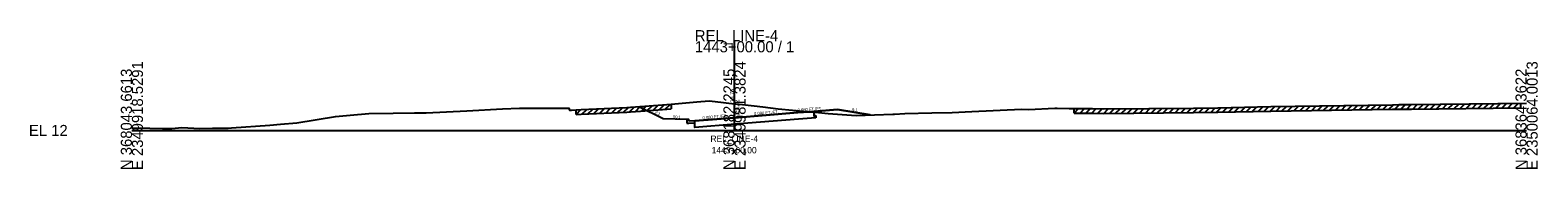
# Model space of a CAD drawing. Extents: x -26 to 2350146, y -10 to 368200.
# Drawn here: x 1974.3 to 2355, y 2990.3 to 3025.3 of the extents above; entities that cross this region are included whole.
import ezdxf

# ---------------------------------------------------------------- set-up
doc = ezdxf.new("R2010")
doc.units = 0
for name, color, linetype in [('RD_GPK_XS_Cell', 7, 'Continuous'), ('RD_XS_Base', 7, 'Continuous'), ('RD_XS_CurbBase', 7, 'Continuous'), ('RD_XS_CurbFront', 7, 'Continuous'), ('RD_XS_CurbTop', 7, 'Continuous'), ('RD_XS_EarthShd', 7, 'Continuous'), ('RD_XS_EwShp', 7, 'Continuous'), ('RD_XS_ExGround', 7, 'Continuous'), ('RD_XS_ExPaveRet', 7, 'Continuous'), ('RD_XS_Pave', 7, 'Continuous'), ('RD_XS_PaveShd', 7, 'Continuous'), ('RD_XS_TieSlope', 7, 'Continuous'), ('RD_XS_TX_Elev_EX', 7, 'Continuous'), ('RD_XS_TX_Elev_PR', 7, 'Continuous'), ('RD_XS_TX_Slope', 7, 'Continuous'), ('RD_XS_TX_Station', 7, 'Continuous'), ('RD_XS_TX_TOC', 7, 'Continuous')]:
    doc.layers.add(name, color=color, linetype=linetype)

msp = doc.modelspace()

# ---------------------------------------------------------------- linework, layer by layer
at = {"layer": 'RD_GPK_XS_Cell'}
for p, q in [((2152.15, 3000), (2152.15, 3022.53)), ((2000, 3000), (2152.15, 3000)), ((2152.15, 3000), (2352.15, 3000))]:
    msp.add_line(p, q, dxfattribs=at)
at = {"layer": 'RD_XS_Base'}
for p, q in [((2172.16, 3004.82), (2172.16, 3003.68)), ((2172.66, 3003.72), (2172.66, 3003.22)), ((2142.15, 3000.78), (2142.15, 3001.9)), ((2152.28, 3001.59), (2142.15, 3000.78)), ((2168.28, 3002.87), (2152.28, 3001.59)), ((2172.66, 3003.22), (2168.28, 3002.87))]:
    msp.add_line(p, q, dxfattribs=at)
at = {"layer": 'RD_XS_CurbBase'}
for p, q in [((2172.66, 3003.72), (2172.16, 3003.68)), ((2140.15, 3002.81), (2140.15, 3001.81)), ((2140.15, 3001.81), (2140.65, 3001.81)), ((2140.65, 3001.81), (2142.15, 3001.9))]:
    msp.add_line(p, q, dxfattribs=at)
at = {"layer": 'RD_XS_CurbFront'}
msp.add_line((2142.15, 3001.9), (2142.15, 3002.4), dxfattribs=at)
at = {"layer": 'RD_XS_CurbTop'}
for p, q in [((2140.65, 3002.81), (2140.15, 3002.81)), ((2140.73, 3002.31), (2140.65, 3002.81)), ((2142.15, 3002.4), (2140.73, 3002.31)), ((2142.15, 3002.42), (2142.15, 3002.4))]:
    msp.add_line(p, q, dxfattribs=at)
at = {"layer": 'RD_XS_EarthShd'}
for p, q in [((2172.16, 3004.82), (2178.15, 3005.3)), ((2178.15, 3005.3), (2186.42, 3003.92)), ((2140.15, 3002.81), (2134.15, 3002.93))]:
    msp.add_line(p, q, dxfattribs=at)
at = {"layer": 'RD_XS_EwShp'}
for points in [[(2140.15, 3002.81), (2134.15, 3002.93), (2128, 3006.01), (2128.39, 3006.04), (2136.18, 3006.6), (2142.67, 3007.22), (2145.77, 3007.51), (2147.25, 3007.32), (2152.15, 3006.75), (2154.13, 3006.52), (2159.32, 3005.95), (2163.16, 3005.5), (2170.45, 3004.8), (2171.11, 3004.73), (2168.15, 3004.5), (2152.15, 3003.22), (2142.15, 3002.4), (2140.73, 3002.31), (2140.65, 3002.81)], [(2172.66, 3003.22), (2168.28, 3002.87), (2152.28, 3001.59), (2142.15, 3000.78), (2142.15, 3001.9), (2142.15, 3002.4), (2152.15, 3003.22), (2168.15, 3004.5), (2171.11, 3004.73), (2172.16, 3004.62), (2172.16, 3003.68), (2172.66, 3003.72)], [(2172.16, 3004.62), (2173.33, 3004.5), (2175.77, 3004.32), (2182.86, 3003.8), (2186.42, 3003.92), (2178.15, 3005.3), (2172.16, 3004.82)], [(2140.15, 3001.81), (2140.65, 3001.81), (2142.15, 3001.9), (2142.15, 3002.4), (2140.73, 3002.31), (2140.65, 3002.81), (2140.15, 3002.81)]]:
    msp.add_lwpolyline(points, close=True, dxfattribs=at)
at = {"layer": 'RD_XS_ExGround'}
msp.add_lwpolyline([(2000, 3000.7), (2004.53, 3000.54), (2007.71, 3000.53), (2010.04, 3000.52), (2012.59, 3000.77), (2017.14, 3000.5), (2020.31, 3000.56), (2024.3, 3000.59), (2025.12, 3000.66), (2034.83, 3001.37), (2037.52, 3001.56), (2041.65, 3001.93), (2051.41, 3003.49), (2056.07, 3003.96), (2058.86, 3004.23), (2059.79, 3004.29), (2065.98, 3004.38), (2071.33, 3004.45), (2073.08, 3004.49), (2074.33, 3004.49), (2084.6, 3004.98), (2093.57, 3005.5), (2097.84, 3005.59), (2099.12, 3005.61), (2102.2, 3005.62), (2106.81, 3005.66), (2109.75, 3005.65), (2110.31, 3005.64), (2110.48, 3005.14), (2110.98, 3005.16), (2112.14, 3005.2), (2113.41, 3005.26), (2125, 3005.8), (2125.85, 3005.86), (2128.39, 3006.04), (2136.18, 3006.6), (2142.67, 3007.22), (2145.77, 3007.51), (2147.25, 3007.32), (2152.15, 3006.75), (2154.13, 3006.52), (2159.32, 3005.95), (2163.16, 3005.5), (2170.45, 3004.8), (2173.33, 3004.5), (2175.77, 3004.32), (2182.86, 3003.8), (2192.16, 3004.11), (2192.57, 3004.12), (2195.14, 3004.25), (2202.01, 3004.48), (2207.08, 3004.55), (2212.08, 3004.81), (2224.65, 3005.35), (2226.36, 3005.33), (2233.07, 3005.65), (2233.6, 3005.6), (2236.69, 3005.54), (2237.89, 3005.51), (2242.52, 3005.53), (2245.37, 3005.46), (2268.08, 3005.64), (2274.22, 3005.74), (2287.55, 3006.03), (2318.26, 3006.5), (2319.89, 3006.52), (2320.35, 3006.53), (2321.19, 3006.54), (2323.13, 3006.55), (2352.15, 3006.87)], dxfattribs=at)
at = {"layer": 'RD_XS_ExPaveRet'}
for p, q in [((2112.14, 3004.06), (2113.34, 3005.26)), ((2112.14, 3004.06), (2112.14, 3005.2)), ((2112.14, 3004.06), (2113.41, 3004.12)), ((2113.41, 3004.12), (2125, 3004.66)), ((2113.64, 3004.13), (2114.84, 3005.33)), ((2115.14, 3004.2), (2116.34, 3005.4)), ((2116.64, 3004.27), (2117.84, 3005.47)), ((2118.14, 3004.34), (2119.34, 3005.54)), ((2119.64, 3004.41), (2120.84, 3005.61)), ((2121.14, 3004.48), (2122.34, 3005.67)), ((2122.64, 3004.55), (2123.84, 3005.74)), ((2124.14, 3004.62), (2125.35, 3005.82)), ((2125, 3004.66), (2125.85, 3004.71)), ((2125.64, 3004.7), (2126.87, 3005.93)), ((2125.85, 3004.71), (2128.39, 3004.89)), ((2127.14, 3004.81), (2128.37, 3006.04)), ((2128.39, 3004.89), (2136.18, 3005.46)), ((2128.64, 3004.91), (2129.87, 3006.14)), ((2130.14, 3005.02), (2131.37, 3006.25)), ((2131.64, 3005.13), (2132.87, 3006.36)), ((2133.14, 3005.24), (2134.37, 3006.47)), ((2134.64, 3005.35), (2135.87, 3006.58)), ((2136.18, 3006.6), (2136.18, 3005.46)), ((2237.89, 3004.37), (2239.04, 3005.52)), ((2237.89, 3004.37), (2237.89, 3005.51)), ((2237.89, 3004.37), (2242.52, 3004.39)), ((2239.39, 3004.37), (2240.54, 3005.52)), ((2240.89, 3004.38), (2242.04, 3005.53)), ((2242.39, 3004.39), (2243.5, 3005.51)), ((2242.52, 3004.39), (2245.37, 3004.32)), ((2243.89, 3004.36), (2245, 3005.47)), ((2245.37, 3004.32), (2268.08, 3004.5)), ((2245.39, 3004.32), (2246.54, 3005.47)), ((2246.89, 3004.33), (2248.04, 3005.48)), ((2248.39, 3004.34), (2249.54, 3005.49)), ((2249.89, 3004.35), (2251.04, 3005.5)), ((2251.39, 3004.36), (2252.54, 3005.52)), ((2252.89, 3004.38), (2254.04, 3005.53)), ((2254.39, 3004.39), (2255.54, 3005.54)), ((2255.89, 3004.4), (2257.04, 3005.55)), ((2257.39, 3004.41), (2258.54, 3005.56)), ((2258.89, 3004.42), (2260.04, 3005.57)), ((2260.39, 3004.43), (2261.54, 3005.59)), ((2261.89, 3004.45), (2263.04, 3005.6)), ((2263.39, 3004.46), (2264.54, 3005.61)), ((2264.89, 3004.47), (2266.04, 3005.62)), ((2266.39, 3004.48), (2267.54, 3005.63)), ((2267.89, 3004.49), (2269.05, 3005.65)), ((2268.08, 3004.5), (2274.22, 3004.6)), ((2269.39, 3004.52), (2270.55, 3005.68)), ((2270.89, 3004.54), (2272.05, 3005.7)), ((2272.39, 3004.57), (2273.55, 3005.73)), ((2273.89, 3004.59), (2275.05, 3005.76)), ((2274.22, 3004.6), (2287.55, 3004.89)), ((2275.39, 3004.62), (2276.55, 3005.79)), ((2276.89, 3004.66), (2278.05, 3005.82)), ((2278.39, 3004.69), (2279.55, 3005.86)), ((2279.89, 3004.72), (2281.05, 3005.89)), ((2281.39, 3004.75), (2282.55, 3005.92)), ((2282.89, 3004.79), (2284.05, 3005.95)), ((2284.39, 3004.82), (2285.55, 3005.99)), ((2285.89, 3004.85), (2287.05, 3006.02)), ((2287.39, 3004.88), (2288.55, 3006.04)), ((2287.55, 3004.89), (2318.26, 3005.35)), ((2288.89, 3004.91), (2290.05, 3006.07)), ((2290.39, 3004.93), (2291.55, 3006.09)), ((2291.89, 3004.95), (2293.05, 3006.11)), ((2293.39, 3004.98), (2294.55, 3006.14)), ((2294.89, 3005), (2296.05, 3006.16)), ((2296.39, 3005.02), (2297.55, 3006.18)), ((2297.89, 3005.04), (2299.05, 3006.2)), ((2299.39, 3005.07), (2300.55, 3006.23)), ((2300.89, 3005.09), (2302.05, 3006.25)), ((2302.39, 3005.11), (2303.55, 3006.27)), ((2303.89, 3005.13), (2305.05, 3006.3)), ((2305.39, 3005.16), (2306.55, 3006.32)), ((2306.89, 3005.18), (2308.05, 3006.34)), ((2308.39, 3005.2), (2309.55, 3006.36)), ((2309.89, 3005.23), (2311.05, 3006.39)), ((2311.39, 3005.25), (2312.55, 3006.41)), ((2312.89, 3005.27), (2314.05, 3006.43)), ((2314.39, 3005.29), (2315.55, 3006.45)), ((2315.89, 3005.32), (2317.05, 3006.48)), ((2317.39, 3005.34), (2318.55, 3006.5)), ((2318.26, 3005.35), (2319.89, 3005.38)), ((2318.89, 3005.36), (2320.05, 3006.53)), ((2319.89, 3005.38), (2320.35, 3005.39)), ((2320.35, 3005.39), (2321.19, 3005.39)), ((2320.39, 3005.39), (2321.54, 3006.54)), ((2321.19, 3005.39), (2323.13, 3005.41)), ((2321.89, 3005.4), (2323.04, 3006.55)), ((2323.13, 3005.41), (2350.64, 3005.71)), ((2323.39, 3005.41), (2324.54, 3006.57)), ((2324.89, 3005.43), (2326.04, 3006.58)), ((2326.39, 3005.45), (2327.54, 3006.6)), ((2327.89, 3005.46), (2329.04, 3006.62)), ((2329.39, 3005.48), (2330.54, 3006.63)), ((2330.89, 3005.49), (2332.04, 3006.65)), ((2332.39, 3005.51), (2333.54, 3006.67)), ((2333.89, 3005.53), (2335.04, 3006.68)), ((2335.39, 3005.54), (2336.54, 3006.7)), ((2336.89, 3005.56), (2338.04, 3006.72)), ((2338.39, 3005.58), (2339.54, 3006.73)), ((2339.89, 3005.59), (2341.04, 3006.75)), ((2341.39, 3005.61), (2342.54, 3006.76)), ((2342.89, 3005.62), (2344.04, 3006.78)), ((2344.39, 3005.64), (2345.54, 3006.8)), ((2345.89, 3005.66), (2347.04, 3006.81)), ((2347.39, 3005.67), (2348.54, 3006.83)), ((2348.89, 3005.69), (2350.04, 3006.85)), ((2350.64, 3006.85), (2350.64, 3005.71))]:
    msp.add_line(p, q, dxfattribs=at)
at = {"layer": 'RD_XS_Pave'}
for p, q in [((2168.15, 3004.5), (2152.15, 3003.22)), ((2152.15, 3003.22), (2142.15, 3002.42))]:
    msp.add_line(p, q, dxfattribs=at)
at = {"layer": 'RD_XS_PaveShd'}
msp.add_line((2172.16, 3004.82), (2168.15, 3004.5), dxfattribs=at)
at = {"layer": 'RD_XS_TieSlope'}
msp.add_line((2134.15, 3002.93), (2128, 3006.01), dxfattribs=at)

# ---------------------------------------------------------------- texts
at = {"layer": 'RD_GPK_XS_Cell'}
for s, p in [('1443+00.00 / 1', (2142.15, 3019.73)), ('REL_LINE-4', (2142.15, 3022.53)), ('EL 12', (1974, 2998.6))]:
    msp.add_text(s, height=2.8, dxfattribs=at).set_placement(p)
for s, p in [('N 368043.6613', (2000, 2990)), ('E 2349918.5291', (2002.8, 2990)), ('N 368182.2245', (2152.15, 2990)), ('E 2349981.3824', (2154.95, 2990)), ('N 368364.3622', (2352.15, 2990)), ('E 2350064.0013', (2354.95, 2990))]:
    msp.add_text(s, height=2.8, rotation=90, dxfattribs=at).set_placement(p)
at = {"layer": 'RD_XS_TX_Elev_EX'}
msp.add_text('18.75', height=1, rotation=90, dxfattribs=at).set_placement((2152.02, 3007.06))
at = {"layer": 'RD_XS_TX_Elev_PR'}
msp.add_text(' 15.22', height=1.2, rotation=90, dxfattribs=at).set_placement((2153.35, 3003.22))
at = {"layer": 'RD_XS_TX_Slope'}
for s, rotation, p in [('2:1', 333.4349, (2131.95, 3004.38)), ('50:1', 358.8542, (2136.6, 3003.06)), ('0.080 FT./FT.', 4.5739, (2144.11, 3002.82)), ('0.080 FT./FT.', 4.5739, (2157.11, 3003.86)), ('0.080 FT./FT.', 4.5739, (2168.11, 3004.74)), ('6:1', 350.5377, (2181.77, 3004.99))]:
    msp.add_text(s, height=0.75, rotation=rotation, dxfattribs=at).set_placement(p)
at = {"layer": 'RD_XS_TX_Station'}
for s, p in [('REL_LINE-4', (2146.08, 2997.12)), ('1443+00.00', (2146.38, 2994.22))]:
    msp.add_text(s, height=1.6, dxfattribs=at).set_placement(p)
at = {"layer": 'RD_XS_TX_TOC'}
msp.add_text('TOCLT', height=0.05, dxfattribs=at).set_placement((2140.7, 3002.76))

doc.saveas('drawing.dxf')
